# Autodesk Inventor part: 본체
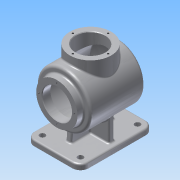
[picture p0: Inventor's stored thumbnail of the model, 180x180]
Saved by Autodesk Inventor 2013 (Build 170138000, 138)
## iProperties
Created: 2016-09
Part Number: 본체
Material: 알루미늄 6061
Document SubType Name: Modeling
Designer: Administrator
Density: 2.71 g/cm^3
Mass: 972.179 g
Surface Area: 1283.63 cm^2
Volume: 358.738 cm^3
Author: Administrator
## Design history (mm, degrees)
sketch "스케치1"
  geometry: L1 (-67.5, 50)-(67.5, 50); L2 (67.5, 50)-(67.5, -50); L3 (67.5, -50)-(-67.5, -50); L4 (-67.5, -50)-(-67.5, 50); L5 (67.5, -50)-(-67.5, 50); 2 further points
  constraints: 10 end point, 2 parallel, 1 coincident, 1 horizontal, 1 midpoint, 1 perpendicular
  dimensions: "d0" = 135 distance of L1.start L1.end; "d2" = 100 distance of L1.end L2.end
extrude "돌출1" new body sketch "스케치1" distance "d3" = 10; taper "d4" = 0 deg
fillet "모깎기1" dims "d5" = 15
hole "구멍1" diameter "d8" = 10; stored, may be unused: countersink angle "d12" = 90 deg, drill point angle "d14" = 0 deg; dims "d6" = 10, "d7" = 10, "d9" = 6, "d10" = 4, "d11" = 2, "d13" = 8
hole "구멍2" diameter "d17" = 10; stored, may be unused: countersink angle "d21" = 90 deg, drill point angle "d23" = 0 deg; dims "d15" = 10, "d16" = 10, "d18" = 6, "d19" = 4, "d20" = 2, "d22" = 8
hole "구멍3" diameter "d26" = 10; stored, may be unused: countersink angle "d30" = 90 deg, drill point angle "d32" = 0 deg; dims "d24" = 10, "d25" = 10, "d27" = 6, "d28" = 4, "d29" = 2, "d31" = 8
hole "구멍4" diameter "d35" = 10; stored, may be unused: countersink angle "d39" = 90 deg, drill point angle "d41" = 0 deg; dims "d33" = 10, "d34" = 10, "d36" = 6, "d37" = 4, "d38" = 2, "d40" = 8
fillet "모깎기2" dims "d42" = 3
sketch "스케치3"
  geometry: L1 (-64.5, 10)-(64.5, 10) reference; L2 (67.5, 7)-(67.5, 0) reference; L3 (67.5, 0)-(-67.5, 0) reference; L4 (-67.5, 0)-(-67.5, 7) reference; L5 (0, 0)-(0, 82); L6 (-44, 132)-(46.374, 132); L7 (61, 132)-(61, 82); L8 (61, 82)-(-61, 82); L9 (-61, 82)-(-61, 132); L10 (-61, 120)-(-49, 120); L11 (-49, 120)-(-49, 127); L12 (46.374, 129)-(-44, 129); L13 (-46, 127)-(-46, 82); L14 (-61, 82)-(61, 82); A1 r 3 centre (-64.5, 7) between (-64.5, 10) and (-67.5, 7) reference; A2 r 3 centre (64.5, 7) between (67.5, 7) and (64.5, 10) reference; A3 r 115 centre (-54, 82) between (26.629, 0) and (35.672, 10); A4 r 115 centre (-54, 82) between (61, 82) and (50.937, 129.045); A5 r 112 centre (-54, 82) between (58, 82) and (48.199, 127.818); A6 r 2 centre (-44, 127) between (-44, 129) and (-46, 127); A7 r 2 centre (46.374, 127) between (48.199, 127.818) and (46.374, 129); A8 r 5 centre (-44, 127) between (-44, 132) and (-49, 127); A9 r 5 centre (46.374, 127) between (50.937, 129.045) and (46.374, 132); 3 further points
  constraints: 20 end point, 16 point on circle, 10 point on line, 9 tangent, 7 centre point, 5 perpendicular, 3 parallel, 2 equal radius, 1 collinear, 1 horizontal, 1 midpoint
  dimensions: "d44" = 82 distance of L5.end L5.start; "d45" = 122 distance of L9.end L7.start; "d47" = 76 diameter of L10 L8; "d48" = 100 diameter of L6 L8; "d50" = 115 radius of A4; "d51" = 3 radial gap between concentric circles of A4 A5; "d52" = 3 distance between parallel lines of L6 L12; "d53" = 3 distance between parallel lines of L11 L13; "d54" = 2 radius of A6; "d55" = 5 radius of A8; "d56" = 12 distance of L10.start L10.end
revolve "회전1" sketch "스케치3" stored, may be unused: angle "d57" = 90 deg
sketch "스케치4"
  geometry: L1 (-64.5, 10)-(64.5, 10) reference; L2 (67.5, 7)-(67.5, 0) reference; L3 (67.5, 0)-(-67.5, 0) reference; L4 (-67.5, 0)-(-67.5, 7) reference; L5 (-61, 44)-(-61, 120) reference; L6 (-61, 120)-(-49, 120) reference; L7 (-49, 120)-(-49, 127) reference; L8 (-44, 132)-(46.374, 132) reference; L9 (46.374, 32)-(-44, 32) reference; L10 (-49, 37)-(-49, 44) reference; L11 (-49, 44)-(-61, 44) reference; L12 (46.374, 129)-(-44, 129); L13 (-46, 127)-(-46, 117); L14 (-46, 117)-(-58, 117); L15 (-58, 117)-(-58, 82); L16 (-58, 82)-(58, 82); L17 (-46, 117)-(-46, 82); A1 r 3 centre (-64.5, 7) between (-64.5, 10) and (-67.5, 7) reference; A2 r 3 centre (64.5, 7) between (67.5, 7) and (64.5, 10) reference; A3 r 5 centre (-44, 127) between (-44, 132) and (-49, 127) reference; A4 r 5 centre (46.374, 127) between (50.937, 129.045) and (46.374, 132) reference; A5 r 115 centre (-54, 82) between (50.937, 34.955) and (50.937, 129.045) reference; A6 r 5 centre (46.374, 37) between (46.374, 32) and (50.937, 34.955) reference; A7 r 5 centre (-44, 37) between (-49, 37) and (-44, 32) reference; A8 r 2 centre (-44, 127) between (-44, 129) and (-46, 127); A9 r 112 centre (-54, 82) between (58, 82) and (48.199, 127.818); A10 r 2 centre (46.374, 127) between (48.199, 127.818) and (46.374, 129); 1 further point
  constraints: 12 end point, 6 point on circle, 3 centre point, 1 point on line, 3 other
  dimensions: "d58" = 3 distance between parallel lines of L12 L8
revolve "회전2" sketch "스케치4" stored, may be unused: angle "d59" = 90 deg
hole "구멍5" diameter "d62" = 54; stored, may be unused: countersink angle "d66" = 90 deg, drill point angle "d68" = 0 deg; dims "d60" = 10, "d61" = 10, "d63" = 6, "d64" = 4, "d65" = 2, "d67" = 20
node "작업 평면1"
sketch "스케치5"
  geometry: L1 (-46.374, 50)-(-46.374, -50) reference; L2 (49, 45)-(49, -45) reference; L3 (52.5, 50)-(-52.5, 50) reference; L4 (44, -50)-(-46.374, -50) reference; C1 r 38 at (-1, 0)
  constraints: 1 centre point
  dimensions: "d70" = 76 diameter of C1; "d133" = 50 distance from line of L2 C1.centre; "d134" = 50 distance from line of L4 C1.centre
extrude "돌출2" join sketch "스케치5" stored distance "d71" = 10; taper "d72" = 0 deg
hole "구멍6" diameter "d75" = 54; stored, may be unused: countersink angle "d79" = 90 deg, drill point angle "d81" = 0 deg; dims "d73" = 10, "d74" = 10, "d76" = 6, "d77" = 4, "d78" = 2, "d80" = 50
fillet "모깎기3" dims "d82" = 3
chamfer "모따기1" distance "d83" = 1; stored, may be unused: second distance "d84" = 2, angle "d85" = 45 deg
sketch "스케치6"
  geometry: L1 (-32.5, 0)-(32.5, 0); C1 r 28 at (0, 0) reference; C2 r 38 at (0, 0) reference; 2 further points
  constraints: 2 coincident, 2 end point, 1 horizontal, 1 midpoint
  dimensions: "d86" = 65 distance of L1.start L1.end
hole "구멍7" sketch "스케치6" at (-32.5, 0) diameter "d88" = 3.459; stored, may be unused: countersink angle "d92" = 90 deg, drill point angle "d94" = 118 deg; dims "d89" = 8, "d90" = 4, "d91" = 2, "d93" = 10
sketch "스케치7"
  geometry: L1 (75, 47.359)-(82, 47.359) reference; L2 (82, 47.359)-(82, -47.359) reference; L3 (82, -47.359)-(75, -47.359) reference; L4 (72, -43.471)-(72, 43.471) reference; L5 (32.5, 0)-(-32.5, 0); C1 r 28 at (0, 0) reference; C2 r 38 at (0, 0) reference; 3 further points
  constraints: 2 coincident, 2 end point, 1 midpoint, 1 perpendicular, 2 other
  dimensions: "d98" = 65 distance of L5.start L5.end
hole "구멍8" sketch "스케치7" at (-32.5, 0) diameter "d100" = 3.459; stored, may be unused: countersink angle "d104" = 90 deg, drill point angle "d106" = 118 deg; dims "d101" = 8, "d102" = 4, "d103" = 2, "d105" = 10
sketch "스케치9"
  geometry: L1 (-46, 127)-(-46, 109) reference; L2 (-46, 109)-(-60, 109) reference; L3 (-60, 109)-(-61, 110) reference; L4 (-61, 110)-(-61, 112.77) reference; L5 (-61, 112.77)-(-51, 112.77) reference; L6 (-51, 112.77)-(-49.961, 114.5) reference; L7 (-49.961, 114.5)-(-51, 116.23) reference; L8 (-51, 116.23)-(-61, 116.23) reference; L9 (-61, 116.23)-(-61, 120) reference; L10 (-61, 120)-(-52, 120) reference; L11 (-49, 123)-(-49, 127) reference; L12 (-44, 132)-(-40, 132) reference; L13 (-37, 135)-(-37, 147) reference; L14 (-37, 147)-(-33.23, 147) reference; L15 (-33.23, 147)-(-33.23, 137) reference; L16 (-33.23, 137)-(-31.5, 135.961) reference; L17 (-31.5, 135.961)-(-29.771, 137) reference; L18 (-29.771, 137)-(-29.771, 147) reference; L19 (-29.771, 147)-(-27, 147) reference; L20 (-27, 147)-(-26, 146) reference; L21 (-26, 146)-(-26, 129) reference; L22 (-26, 129)-(-44, 129) reference; L23 (-64.5, 10)-(64.5, 10) reference; L24 (46.374, 32)-(-44, 32) reference; L25 (-49, 37)-(-49, 41) reference; L26 (-52, 44)-(-61, 44) reference; L27 (-61, 44)-(-61, 47.77) reference; L28 (-61, 47.77)-(-51, 47.77) reference; L29 (-51, 47.77)-(-49.961, 49.5) reference; L30 (-49.961, 49.5)-(-51, 51.229) reference; L31 (-51, 51.229)-(-61, 51.229) reference; L32 (-61, 51.229)-(-61, 54) reference; L33 (-61, 54)-(-60, 55) reference; L34 (-60, 55)-(-46, 55) reference; L35 (-46, 55)-(-46, 37) reference; L36 (-44, 35)-(46.374, 35) reference; L37 (46.374, 129)-(28, 129) reference; L38 (28, 129)-(28, 146) reference; L39 (28, 146)-(29, 147) reference; L40 (29, 147)-(31.77, 147) reference; L41 (31.77, 147)-(31.77, 137) reference; L42 (31.77, 137)-(33.5, 135.961) reference; L43 (33.5, 135.961)-(35.229, 137) reference; L44 (35.229, 137)-(35.229, 147) reference; L45 (35.229, 147)-(39, 147) reference; L46 (39, 147)-(39, 135) reference; L47 (42, 132)-(46.374, 132) reference; L48 (67.5, 7)-(67.5, 0) reference; L49 (67.5, 0)-(-67.5, 0) reference; L50 (-67.5, 0)-(-67.5, 7) reference; L51 (-38.075, 32)-(-40, 10); L52 (0, 0)-(0, 67.844); L53 (38.075, 32)-(40, 10); A1 r 2 centre (-44, 127) between (-44, 129) and (-46, 127) reference; A2 r 3 centre (-52, 123) between (-52, 120) and (-49, 123) reference; A3 r 5 centre (-44, 127) between (-44, 132) and (-49, 127) reference; A4 r 3 centre (-64.5, 7) between (-64.5, 10) and (-67.5, 7) reference; A5 r 5 centre (-44, 37) between (-49, 37) and (-44, 32) reference; A6 r 3 centre (-52, 41) between (-49, 41) and (-52, 44) reference; A7 r 2 centre (-44, 37) between (-46, 37) and (-44, 35) reference; A8 r 2 centre (46.374, 37) between (46.374, 35) and (48.199, 36.182) reference; A9 r 112 centre (-54, 82) between (48.199, 36.182) and (48.199, 127.818) reference; A10 r 2 centre (46.374, 127) between (48.199, 127.818) and (46.374, 129) reference; A11 r 5 centre (46.374, 127) between (50.937, 129.045) and (46.374, 132) reference; A12 r 115 centre (-54, 82) between (50.937, 34.955) and (50.937, 129.045) reference; A13 r 5 centre (46.374, 37) between (46.374, 32) and (50.937, 34.955) reference; A14 r 3 centre (64.5, 7) between (67.5, 7) and (64.5, 10) reference
  constraints: 6 end point, 2 point on line, 2 symmetric about line, 1 parallel, 2 other
  dimensions: "d114" = 40 horizontal distance of L52.start L51.end; "d115" = 95 deg angle of L23 L51
  node "절단 모서리 투영6"
node "작업 평면2"
sketch "스케치10"
  geometry: L1 (43.292, 7)-(43.292, 0) reference; L2 (43.292, 0)-(-43.292, 0) reference; L3 (-43.292, 0)-(-43.292, 7) reference; L4 (-35, 9.958)-(35, 9.958) reference; L5 (35, 0)-(-35, 0) reference; L6 (-26.132, 94.195)-(26.132, 94.195); L7 (26.132, 94.195)-(26.132, 69.805); L8 (26.132, 69.805)-(-26.132, 69.805); L9 (-26.132, 69.805)-(-26.132, 94.195); L10 (-26.132, 82)-(26.132, 82); L11 (0, 94.195)-(0, 69.805); L12 (0, 82)-(0, 0); C1 r 50 at (0, 82) reference
  constraints: 6 end point, 5 midpoint, 2 collinear, 4 other
feature "엠보싱1" sketch "스케치10" dims "d0" = 135, "d2" = 100, "d24" = 10, "d25" = 10, "d131" = 0.5, "d132" = 0
sketch "스케치11"
  geometry: L1 (-37.987, 115.603)-(-37.987, 147) reference; L2 (-37.987, 147)-(-33.911, 147) reference; L3 (-33.911, 147)-(-33.911, 137) reference; L4 (-31.089, 137)-(-31.089, 147) reference; L5 (-31.089, 147)-(-27.982, 147) reference; L6 (-27.982, 147)-(-26.981, 146) reference; L7 (-26.981, 146)-(-26.981, 120.484) reference; L8 (26.981, 120.484)-(26.981, 146) reference; L9 (26.981, 146)-(27.982, 147) reference; L10 (27.982, 147)-(31.089, 147) reference; L11 (31.089, 147)-(31.089, 137) reference; L12 (33.911, 137)-(33.911, 147) reference; L13 (33.911, 147)-(37.987, 147) reference; L14 (37.987, 147)-(37.987, 115.603) reference; L15 (50, 7)-(50, 0) reference; L16 (50, 0)-(-50, 0) reference; L17 (-50, 0)-(-50, 7) reference; L18 (-47, 10)-(47, 10) reference; L19 (-40, 52)-(-40, 10); L20 (40, 52)-(40, 10); L21 (0, 0)-(0, 82); A1 r 50 centre (0, 82) between (-38.668, 113.699) and (38.668, 113.699) reference; A2 r 47 centre (0, 82) between (-26.981, 120.484) and (26.981, 120.484) reference; A3 r 3 centre (47, 7) between (50, 7) and (47, 10) reference; A4 r 3 centre (-47, 7) between (-47, 10) and (-50, 7) reference
  constraints: 6 end point, 2 horizontal alignment, 2 perpendicular, 2 point on circle, 2 point on line, 1 parallel, 2 other
  dimensions: "d135" = 40 distance between parallel lines of L21 L19; "d136" = 40 distance between parallel lines of L20 L21
extrude "돌출4" join sketch "스케치11" stored distance "d137" = 10; taper "d138" = 0 deg
sketch "스케치12"
  geometry: L1 (-46, 127)-(-46, 109) reference; L2 (-46, 109)-(-60, 109) reference; L3 (-60, 109)-(-61, 110) reference; L4 (-61, 110)-(-61, 112.77) reference; L5 (-61, 112.77)-(-51, 112.77) reference; L6 (-51, 112.77)-(-49.961, 114.5) reference; L7 (-49.961, 114.5)-(-51, 116.23) reference; L8 (-51, 116.23)-(-61, 116.23) reference; L9 (-61, 116.23)-(-61, 120) reference; L10 (-61, 120)-(-52, 120) reference; L11 (-49, 123)-(-49, 127) reference; L12 (-44, 132)-(-40, 132) reference; L13 (-37, 135)-(-37, 147) reference; L14 (-37, 147)-(-33.23, 147) reference; L15 (-33.23, 147)-(-33.23, 137) reference; L16 (-33.23, 137)-(-31.5, 135.961) reference; L17 (-31.5, 135.961)-(-29.771, 137) reference; L18 (-29.771, 137)-(-29.771, 147) reference; L19 (-29.771, 147)-(-27, 147) reference; L20 (-27, 147)-(-26, 146) reference; L21 (-26, 146)-(-26, 129) reference; L22 (-26, 129)-(-44, 129) reference; L23 (46.374, 129)-(28, 129) reference; L24 (28, 129)-(28, 146) reference; L25 (28, 146)-(29, 147) reference; L26 (29, 147)-(31.77, 147) reference; L27 (31.77, 147)-(31.77, 137) reference; L28 (31.77, 137)-(33.5, 135.961) reference; L29 (33.5, 135.961)-(35.229, 137) reference; L30 (35.229, 137)-(35.229, 147) reference; L31 (35.229, 147)-(39, 147) reference; L32 (39, 147)-(39, 135) reference; L33 (42, 132)-(46.374, 132) reference; L34 (60.952, 85.339)-(61.452, 85.339) reference; L35 (61.467, 84.759)-(60.967, 84.759) reference; L36 (46.374, 32)-(5, 32) reference; L37 (5, 32)-(5, 10) reference; L38 (5, 10)-(64.5, 10) reference; L39 (67.5, 7)-(67.5, 0) reference; L40 (67.5, 0)-(-67.5, 0) reference; L41 (-67.5, 0)-(-67.5, 7) reference; L42 (-64.5, 10)-(-5, 10) reference; L43 (-5, 10)-(-5, 32) reference; L44 (-5, 32)-(-44, 32) reference; L45 (-49, 37)-(-49, 41) reference; L46 (-52, 44)-(-61, 44) reference; L47 (-61, 44)-(-61, 47.77) reference; L48 (-61, 47.77)-(-51, 47.77) reference; L49 (-51, 47.77)-(-49.961, 49.5) reference; L50 (-49.961, 49.5)-(-51, 51.229) reference; L51 (-51, 51.229)-(-61, 51.229) reference; L52 (-61, 51.229)-(-61, 54) reference; L53 (-61, 54)-(-60, 55) reference; L54 (-60, 55)-(-46, 55) reference; L55 (-46, 55)-(-46, 37) reference; L56 (-44, 35)-(46.374, 35) reference; L57 (-38.075, 32)-(-40, 10); L58 (0, 0.971)-(0, 54); L59 (38.075, 32)-(40, 10); A1 r 2 centre (-44, 127) between (-44, 129) and (-46, 127) reference; A2 r 3 centre (-52, 123) between (-52, 120) and (-49, 123) reference; A3 r 5 centre (-44, 127) between (-44, 132) and (-49, 127) reference; A4 r 112 centre (-54, 82) between (48.199, 36.182) and (48.199, 127.818) reference; A5 r 2 centre (46.374, 127) between (48.199, 127.818) and (46.374, 129) reference; A6 r 5 centre (46.374, 127) between (50.937, 129.045) and (46.374, 132) reference; A7 r 115 centre (-54, 82) between (60.952, 85.339) and (50.937, 129.045) reference; A8 r 115.5 centre (-54, 82) between (61.467, 84.759) and (61.452, 85.339) reference; A9 r 115 centre (-54, 82) between (50.937, 34.955) and (60.967, 84.759) reference; A10 r 5 centre (46.374, 37) between (46.374, 32) and (50.937, 34.955) reference; A11 r 3 centre (64.5, 7) between (67.5, 7) and (64.5, 10) reference; A12 r 3 centre (-64.5, 7) between (-64.5, 10) and (-67.5, 7) reference; A13 r 5 centre (-44, 37) between (-49, 37) and (-44, 32) reference; A14 r 3 centre (-52, 41) between (-49, 41) and (-52, 44) reference; A15 r 2 centre (-44, 37) between (-46, 37) and (-44, 35) reference; A16 r 2 centre (46.374, 37) between (46.374, 35) and (48.199, 36.182) reference; 1 further point
  constraints: 6 end point, 2 point on line, 2 symmetric about line, 1 perpendicular, 2 other
  dimensions: "d139" = 40 horizontal distance of point (0, 0) L57.end; "d140" = 95 deg angle of L42 L57
  node "절단 모서리 투영9"
feature "리브3" dims "d141" = 1, "d142" = 10, "d143" = 0, "d144" = 0, "d145" = 1, "d146" = 1
feature "리브4" dims "d147" = 1, "d148" = 10, "d149" = 0, "d150" = 0, "d151" = 1, "d152" = 1
fillet "모깎기6" dims "d153" = 3
fillet "모깎기7" dims "d154" = 3
node "솔리드1"
pattern_circular "원형 패턴1" dims angle "d96" = 360 deg
pattern_circular "원형 패턴2" dims angle "d108" = 360 deg
node "절단 모서리 투영1"
node "절단 모서리 투영2"
node "절단 모서리 투영3"
node "절단 모서리 투영4"
node "절단 모서리 투영7"
node "절단 모서리 투영8"
other parameters: "d49" = 115, "d69" = 147, "d130" = -65
